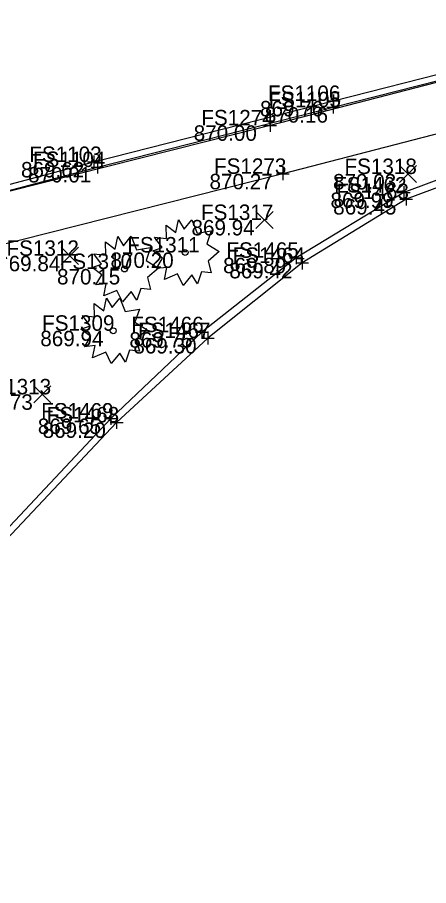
# Model space of a CAD drawing. Extents: x 1479420 to 1479833, y 379731 to 380103.
# Drawn here: x 1479523.1 to 1479555, y 379796.9 to 379864.3 of the extents above; entities that cross this region are included whole.
import ezdxf

# ---------------------------------------------------------------- set-up
doc = ezdxf.new("R2010")
doc.units = 0
for name, color, linetype in [('PV_X_Curb', 7, 'Continuous'), ('PV_X_Walk', 7, 'Continuous'), ('SV_X_Random_Point', 7, 'Continuous'), ('SV_X_Shot_Marker', 7, 'Continuous'), ('SV_X_Text_Elevation', 7, 'Continuous'), ('SV_X_Text_Name', 7, 'Continuous'), ('VG_X_Cells', 7, 'Continuous')]:
    doc.layers.add(name, color=color, linetype=linetype)

msp = doc.modelspace()

# ---------------------------------------------------------------- linework, layer by layer
at = {"layer": 'PV_X_Curb'}
for points in [[(1479448.263, 379811.446), (1479461.223, 379819.505), (1479478.3, 379830.094), (1479484.788, 379833.845), (1479492.119, 379838.16), (1479500.701, 379842.975), (1479508.918, 379847.117), (1479516.087, 379849.63), (1479529.031, 379853.073), (1479547.645, 379857.816), (1479566.743, 379862.68), (1479585.84, 379867.633), (1479595.941, 379870.21)], [(1479448.497, 379810.926), (1479461.699, 379819.081), (1479478.683, 379829.765), (1479485.034, 379833.446), (1479492.452, 379837.857), (1479500.924, 379842.633), (1479509.095, 379846.687), (1479516.116, 379849.207), (1479529.309, 379852.683), (1479547.62, 379857.329), (1479567.188, 379862.296), (1479585.958, 379867.104), (1479596.074, 379869.8)], [(1479601.319, 379856.891), (1479590.521, 379858.038), (1479580.718, 379858.057), (1479571.147, 379856.791), (1479561.287, 379853.753), (1479553.092, 379850.702), (1479544.73, 379845.631), (1479537.421, 379839.852), (1479530.35, 379833.145), (1479518.148, 379820.183), (1479506.748, 379808.804), (1479505.037, 379808.132), (1479502.743, 379808.986), (1479490.356, 379819.723), (1479452.909, 379780.6)], [(1479601.347, 379856.369), (1479590.364, 379857.442), (1479580.925, 379857.48), (1479571.059, 379856.275), (1479561.558, 379853.273), (1479553.285, 379850.192), (1479545.205, 379845.234), (1479537.871, 379839.395), (1479530.786, 379832.841), (1479518.522, 379819.829), (1479508.592, 379809.053), (1479504.774, 379807.6), (1479502.376, 379808.454), (1479490.367, 379818.943), (1479453.507, 379780.799)]]:
    msp.add_lwpolyline(points, dxfattribs=at)
at = {"layer": 'PV_X_Walk'}
for points in [[(1479600.533, 379870.638), (1479580.734, 379865.6), (1479561.549, 379860.766), (1479542.709, 379855.919), (1479519.925, 379850.15), (1479513.475, 379848.178), (1479509.191, 379846.567), (1479504.249, 379844.075), (1479496.362, 379839.934), (1479478.251, 379829.275), (1479450.128, 379811.818)], [(1479601.313, 379866.859), (1479581.547, 379861.918), (1479562.5, 379857.02), (1479543.703, 379852.153), (1479520.939, 379846.407), (1479515.035, 379844.633), (1479510.748, 379842.941), (1479506.291, 379840.861), (1479498.375, 379836.477), (1479480.408, 379825.918), (1479452.204, 379808.527)]]:
    msp.add_lwpolyline(points, dxfattribs=at)
at = {"layer": 'SV_X_Random_Point'}
for p, q in [((1479552.764, 379851.472), (1479554.098, 379852.807)), ((1479552.764, 379852.807), (1479554.098, 379851.472)), ((1479541.608, 379847.902), (1479542.942, 379849.237)), ((1479541.608, 379849.237), (1479542.942, 379847.902)), ((1479526.492, 379845.115), (1479527.826, 379846.45)), ((1479526.492, 379846.45), (1479527.826, 379845.115)), ((1479524.346, 379834.355), (1479525.68, 379835.69)), ((1479524.346, 379835.69), (1479525.68, 379834.355))]:
    msp.add_line(p, q, dxfattribs=at)
at = {"layer": 'SV_X_Shot_Marker'}
for p, q in [((1479547.645, 379858.316), (1479547.645, 379857.316)), ((1479547.145, 379857.816), (1479548.145, 379857.816)), ((1479547.62, 379857.829), (1479547.62, 379856.829)), ((1479547.645, 379857.816), (1479547.645, 379857.816)), ((1479547.12, 379857.329), (1479548.12, 379857.329)), ((1479547.62, 379857.329), (1479547.62, 379857.329)), ((1479542.709, 379856.419), (1479542.709, 379855.419)), ((1479542.209, 379855.919), (1479543.209, 379855.919)), ((1479542.709, 379855.919), (1479542.709, 379855.919)), ((1479528.531, 379853.073), (1479529.531, 379853.073)), ((1479529.031, 379853.573), (1479529.031, 379852.573)), ((1479529.031, 379853.073), (1479529.031, 379853.073)), ((1479529.309, 379853.183), (1479529.309, 379852.183)), ((1479528.809, 379852.683), (1479529.809, 379852.683)), ((1479529.309, 379852.683), (1479529.309, 379852.683)), ((1479543.703, 379852.653), (1479543.703, 379851.653)), ((1479543.203, 379852.153), (1479544.203, 379852.153)), ((1479543.703, 379852.153), (1479543.703, 379852.153)), ((1479553.092, 379851.202), (1479553.092, 379850.202)), ((1479552.592, 379850.702), (1479553.592, 379850.702)), ((1479553.092, 379850.702), (1479553.092, 379850.702)), ((1479553.285, 379850.692), (1479553.285, 379849.692)), ((1479552.785, 379850.192), (1479553.785, 379850.192)), ((1479553.285, 379850.192), (1479553.285, 379850.192)), ((1479544.23, 379845.631), (1479545.23, 379845.631)), ((1479544.73, 379846.131), (1479544.73, 379845.131)), ((1479544.73, 379845.631), (1479544.73, 379845.631)), ((1479545.205, 379845.734), (1479545.205, 379844.734)), ((1479544.705, 379845.234), (1479545.705, 379845.234)), ((1479545.205, 379845.234), (1479545.205, 379845.234)), ((1479537.421, 379840.352), (1479537.421, 379839.352)), ((1479536.921, 379839.852), (1479537.921, 379839.852)), ((1479537.421, 379839.852), (1479537.421, 379839.852)), ((1479537.871, 379839.895), (1479537.871, 379838.895)), ((1479537.371, 379839.395), (1479538.371, 379839.395)), ((1479537.871, 379839.395), (1479537.871, 379839.395)), ((1479530.35, 379833.645), (1479530.35, 379832.645)), ((1479529.85, 379833.145), (1479530.85, 379833.145)), ((1479530.286, 379832.841), (1479531.286, 379832.841)), ((1479530.35, 379833.145), (1479530.35, 379833.145)), ((1479530.786, 379833.341), (1479530.786, 379832.341)), ((1479530.786, 379832.841), (1479530.786, 379832.841))]:
    msp.add_line(p, q, dxfattribs=at)
at = {"layer": 'VG_X_Cells'}
for points in [[(1479536.03, 379847.853), (1479536.635, 379848.588), (1479537.05, 379847.535), (1479538.142, 379847.715), (1479537.803, 379846.703), (1479538.748, 379846.108), (1479537.892, 379845.373), (1479538.142, 379844.46), (1479537.388, 379844.528), (1479537.063, 379843.615), (1479536.635, 379844.306), (1479535.957, 379843.49), (1479535.528, 379844.376), (1479534.508, 379843.946), (1479534.7, 379844.888), (1479533.888, 379844.805), (1479534.362, 379845.595), (1479533.593, 379846.163), (1479534.332, 379846.426), (1479533.725, 379847.23), (1479534.657, 379847.12), (1479534.627, 379848.158), (1479535.38, 379847.59), (1479535.587, 379848.575), (1479536.03, 379847.853)], [(1479531.318, 379846.57), (1479531.923, 379847.305), (1479532.338, 379846.252), (1479533.43, 379846.432), (1479533.091, 379845.42), (1479534.036, 379844.825), (1479533.18, 379844.09), (1479533.43, 379843.177), (1479532.676, 379843.245), (1479532.351, 379842.332), (1479531.923, 379843.023), (1479531.245, 379842.207), (1479530.816, 379843.093), (1479529.796, 379842.663), (1479529.988, 379843.605), (1479529.176, 379843.522), (1479529.65, 379844.312), (1479528.881, 379844.88), (1479529.62, 379845.143), (1479529.013, 379845.947), (1479529.945, 379845.837), (1479529.915, 379846.875), (1479530.668, 379846.307), (1479530.875, 379847.292), (1479531.318, 379846.57)], [(1479530.444, 379841.772), (1479531.049, 379842.507), (1479531.464, 379841.454), (1479532.556, 379841.634), (1479532.217, 379840.622), (1479533.162, 379840.027), (1479532.306, 379839.292), (1479532.556, 379838.379), (1479531.802, 379838.447), (1479531.477, 379837.534), (1479531.049, 379838.226), (1479530.371, 379837.409), (1479529.942, 379838.296), (1479528.922, 379837.866), (1479529.114, 379838.807), (1479528.302, 379838.724), (1479528.776, 379839.514), (1479528.007, 379840.082), (1479528.746, 379840.346), (1479528.139, 379841.149), (1479529.071, 379841.039), (1479529.041, 379842.077), (1479529.794, 379841.509), (1479530.001, 379842.494), (1479530.444, 379841.772)]]:
    msp.add_lwpolyline(points, dxfattribs=at)
for centre in [(1479536.114, 379846.044), (1479531.402, 379844.76), (1479530.528, 379839.963)]:
    msp.add_circle(centre, 0.23, dxfattribs=at)

# ---------------------------------------------------------------- texts
at = {"layer": 'SV_X_Text_Elevation'}
for s, p in [('869.76', (1479541.929, 379856.616)), ('870.16', (1479542.301, 379856.129)), ('870.00', (1479536.776, 379854.719)), ('869.62', (1479523.362, 379851.873)), ('870.01', (1479523.913, 379851.483)), ('870.27', (1479538.006, 379850.953)), ('870.03', (1479547.602, 379850.939)), ('869.99', (1479547.404, 379849.502)), ('869.45', (1479547.616, 379848.992)), ('869.94', (1479536.606, 379847.369)), ('869.84', (1479521.509, 379844.583)), ('870.20', (1479530.314, 379844.843)), ('869.89', (1479539.061, 379844.431)), ('869.42', (1479539.546, 379844.034)), ('870.15', (1479526.16, 379843.56)), ('869.94', (1479524.86, 379838.762)), ('869.75', (1479531.78, 379838.652)), ('869.30', (1479532.089, 379838.195)), ('869.73', (1479519.372, 379833.823)), ('869.65', (1479524.672, 379831.945)), ('869.20', (1479525.041, 379831.641))]:
    msp.add_text(s, height=1.2, dxfattribs=at).set_placement(p)
at = {"layer": 'SV_X_Text_Name'}
for s, p in [('FS1106', (1479542.544, 379857.816)), ('FS1105', (1479542.595, 379857.329)), ('FS1274', (1479537.371, 379855.919)), ('FS1103', (1479524.006, 379853.073)), ('FS1104', (1479524.293, 379852.683)), ('FS1273', (1479538.356, 379852.153)), ('FS1318', (1479548.491, 379852.139)), ('FS1462', (1479547.688, 379850.702)), ('FS1463', (1479547.872, 379850.192)), ('FS1317', (1479537.344, 379848.569)), ('FS1312', (1479522.238, 379845.783)), ('FS1311', (1479531.618, 379846.043)), ('FS1465', (1479539.317, 379845.631)), ('FS1464', (1479539.801, 379845.234)), ('FS1310', (1479526.368, 379844.76)), ('FS1309', (1479525.002, 379839.962)), ('FS1466', (1479531.932, 379839.852)), ('FS1467', (1479532.458, 379839.395)), ('FS1313', (1479520.082, 379835.023)), ('FS1469', (1479524.927, 379833.145)), ('FS1468', (1479525.363, 379832.841))]:
    msp.add_text(s, height=1.2, dxfattribs=at).set_placement(p)

doc.saveas('drawing.dxf')
